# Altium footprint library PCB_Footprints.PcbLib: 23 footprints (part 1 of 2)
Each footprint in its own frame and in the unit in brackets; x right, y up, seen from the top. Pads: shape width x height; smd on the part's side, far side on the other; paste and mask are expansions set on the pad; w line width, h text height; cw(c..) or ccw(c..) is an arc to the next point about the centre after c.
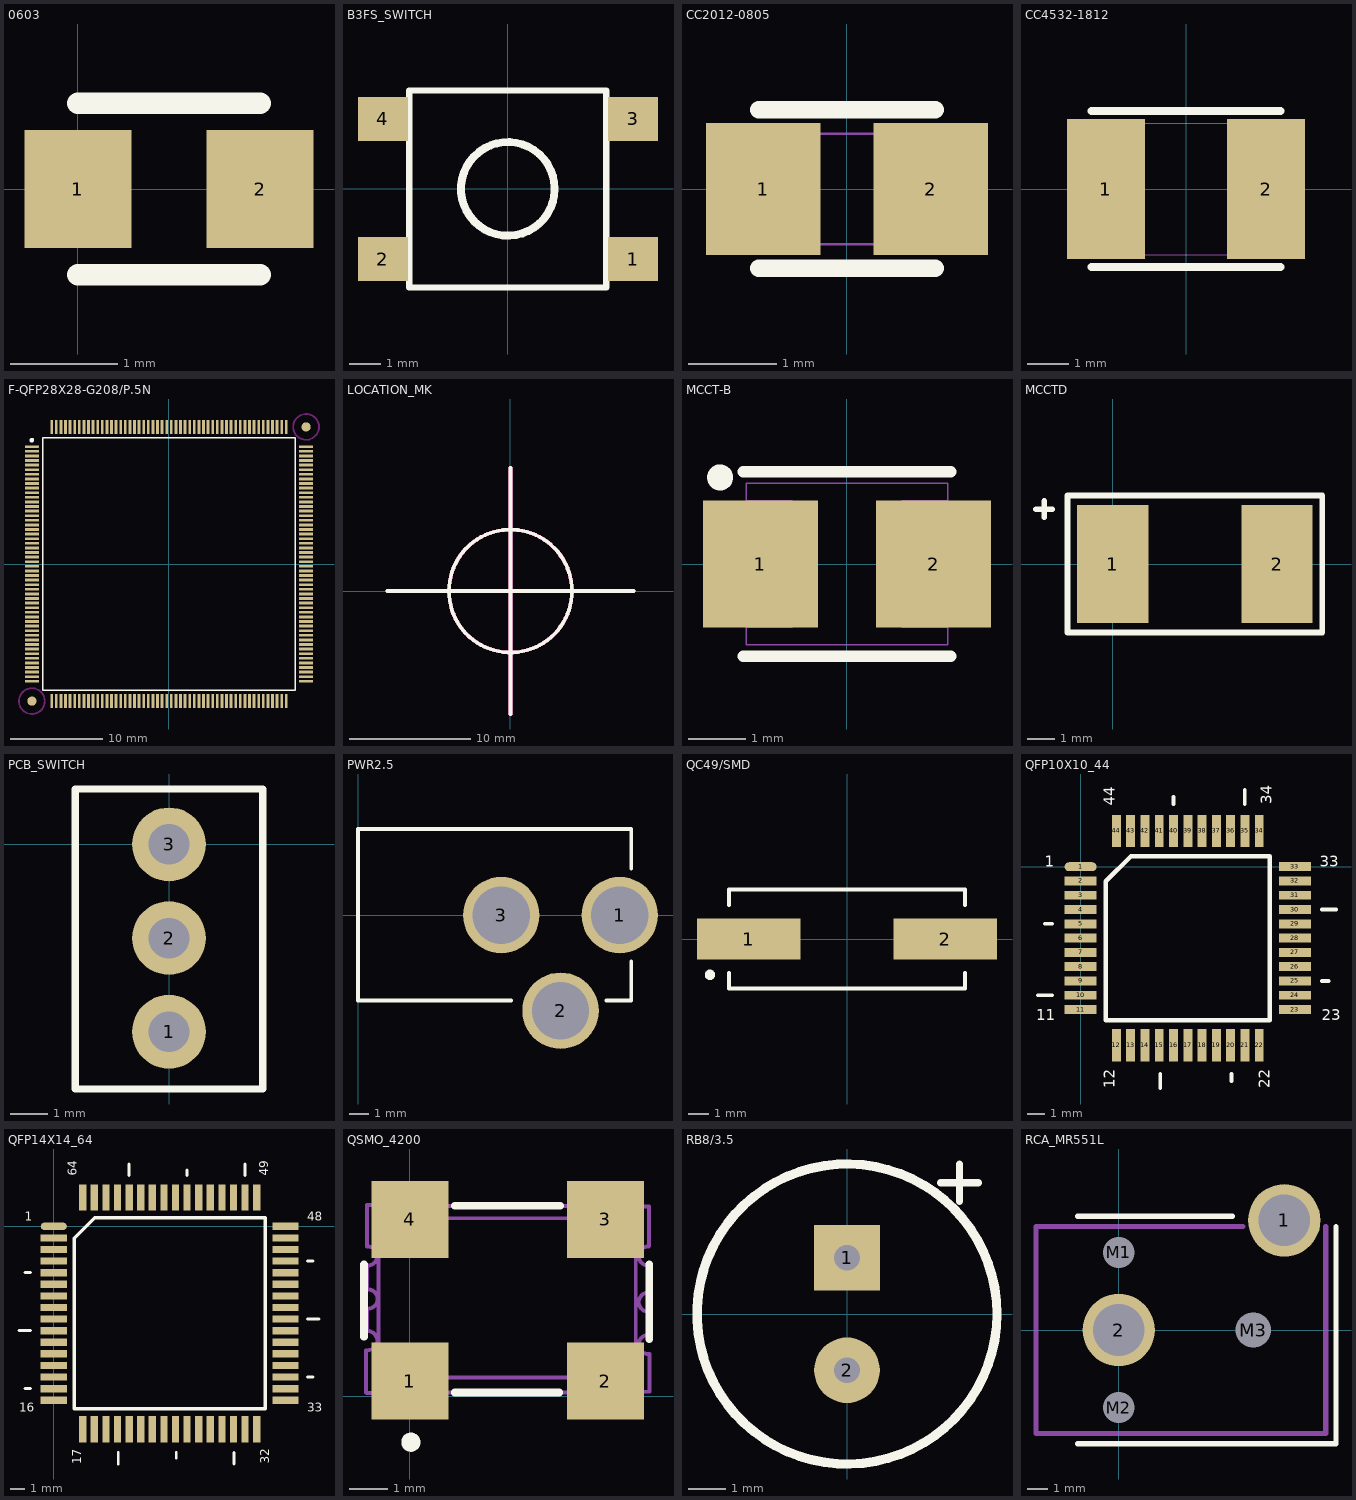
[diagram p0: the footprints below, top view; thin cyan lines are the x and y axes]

## 0603 [mm]
pads (2):
  rect 1x1.1 smd: 1(0,0) 2(1.7,0)
Top Overlay:
  lines w0.203: 0,-0.8 1.7,-0.8 ; 0,0.8 1.7,0.8

## B3FS_SWITCH [mm]
pads (4):
  rect 1.6x1.4 smd: 1(4.01,-2.25) 2(-4,-2.25) 3(4.01,2.24) 4(-4,2.24)
Top Overlay:
  circle w0.254: c0,0 r1.5
  lines w0.2: -3.16,-3.16 -3.16,3.15 3.15,3.15 3.15,-3.16 -3.16,-3.16

## CC2012-0805 [mm]
pads (2):
  rect 1.3x1.5 smd: 1(-0.95,0) 2(0.95,0)
Top Overlay:
  lines w0.2: -1,-0.9 1,-0.9 ; -1,0.9 1,0.9
Mechanical 15:
  lines w0.025: -0.975,-0.625 -0.975,0.625 0.975,0.625 0.975,-0.625 -0.975,-0.625

## CC4532-1812 [mm]
pads (2):
  rect 1.9x3.4 smd: 1(-1.95,0) 2(1.95,0)
Top Overlay:
  lines w0.2: -2.3,-1.9 2.3,-1.9 ; -2.3,1.9 2.3,1.9
Mechanical 15:
  lines w0.025: -2.25,-1.6 -2.25,1.6 2.25,1.6 2.25,-1.6 -2.25,-1.6

## F-QFP28X28-G208/P.5N [mm]
pads (210):
  oval 1.55x0.3 smd: 1(-14.899,12.751)
  rect 1.55x0.3 smd: 2(-14.899,12.251) 3(-14.899,11.751) 4(-14.899,11.251) 5(-14.899,10.751) 6(-14.899,10.251) 7(-14.899,9.751) 8(-14.899,9.251) 9(-14.899,8.751) 10(-14.899,8.251) 11(-14.899,7.751) 12(-14.899,7.251) 13(-14.899,6.751) 14(-14.899,6.251) 15(-14.899,5.751) 16(-14.899,5.251) 17(-14.899,4.751) 18(-14.899,4.251) 19(-14.899,3.751) 20(-14.899,3.251) 21(-14.899,2.751) 22(-14.899,2.251) 23(-14.899,1.751) 24(-14.899,1.251) 25(-14.899,0.751) 26(-14.899,0.251) 27(-14.899,-0.249) 28(-14.899,-0.749) 29(-14.899,-1.249) 30(-14.899,-1.749) 31(-14.899,-2.249) 32(-14.899,-2.749) 33(-14.899,-3.249) 34(-14.899,-3.749) 35(-14.899,-4.249) 36(-14.899,-4.749) 37(-14.899,-5.249) 38(-14.899,-5.749) 39(-14.899,-6.249) 40(-14.899,-6.749) 41(-14.899,-7.249) 42(-14.899,-7.749) 43(-14.899,-8.249) 44(-14.899,-8.749) 45(-14.899,-9.249) 46(-14.899,-9.749) 47(-14.899,-10.249) 48(-14.899,-10.749) 49(-14.899,-11.249) 50(-14.899,-11.749) 51(-14.899,-12.249) 52(-14.899,-12.749) 105(14.901,-12.749) 106(14.901,-12.249) 107(14.901,-11.749) 108(14.901,-11.249) 109(14.901,-10.749) 110(14.901,-10.249) 111(14.901,-9.749) 112(14.901,-9.249) 113(14.901,-8.749) 114(14.901,-8.249) 115(14.901,-7.749) 116(14.901,-7.249) 117(14.901,-6.749) 118(14.901,-6.249) 119(14.901,-5.749) 120(14.901,-5.249) 121(14.901,-4.749) 122(14.901,-4.249) 123(14.901,-3.749) 124(14.901,-3.249) 125(14.901,-2.749) 126(14.901,-2.249) 127(14.901,-1.749) 128(14.901,-1.249) 129(14.901,-0.749) 130(14.901,-0.249) 131(14.901,0.251) 132(14.901,0.751) 133(14.901,1.251) 134(14.901,1.751) 135(14.901,2.251) 136(14.901,2.751) 137(14.901,3.251) 138(14.901,3.751) 139(14.901,4.251) 140(14.901,4.751) 141(14.901,5.251) 142(14.901,5.751) 143(14.901,6.251) 144(14.901,6.751) 145(14.901,7.251) 146(14.901,7.751) 147(14.901,8.251) 148(14.901,8.751) 149(14.901,9.251) 150(14.901,9.751) 151(14.901,10.251) 152(14.901,10.751) 153(14.901,11.251) 154(14.901,11.751) 155(14.901,12.251) 156(14.901,12.751)
  rect 0.3x1.55 smd: 53(-12.749,-14.899) 54(-12.249,-14.899) 55(-11.749,-14.899) 56(-11.249,-14.899) 57(-10.749,-14.899) 58(-10.249,-14.899) 59(-9.749,-14.899) 60(-9.249,-14.899) 61(-8.749,-14.899) 62(-8.249,-14.899) 63(-7.749,-14.899) 64(-7.249,-14.899) 65(-6.749,-14.899) 66(-6.249,-14.899) 67(-5.749,-14.899) 68(-5.249,-14.899) 69(-4.749,-14.899) 70(-4.249,-14.899) 71(-3.749,-14.899) 72(-3.249,-14.899) 73(-2.749,-14.899) 74(-2.249,-14.899) 75(-1.749,-14.899) 76(-1.249,-14.899) 77(-0.749,-14.899) 78(-0.249,-14.899) 79(0.251,-14.899) 80(0.751,-14.899) 81(1.251,-14.899) 82(1.751,-14.899) 83(2.251,-14.899) 84(2.751,-14.899) 85(3.251,-14.899) 86(3.751,-14.899) 87(4.251,-14.899) 88(4.751,-14.899) 89(5.251,-14.899) 90(5.751,-14.899) 91(6.251,-14.899) 92(6.751,-14.899) 93(7.251,-14.899) 94(7.751,-14.899) 95(8.251,-14.899) 96(8.751,-14.899) 97(9.251,-14.899) 98(9.751,-14.899) 99(10.251,-14.899) 100(10.751,-14.899) 101(11.251,-14.899) 102(11.751,-14.899) 103(12.251,-14.899) 104(12.751,-14.899) 157(12.751,14.901) 158(12.251,14.901) 159(11.751,14.901) 160(11.251,14.901) 161(10.751,14.901) 162(10.251,14.901) 163(9.751,14.901) 164(9.251,14.901) 165(8.751,14.901) 166(8.251,14.901) 167(7.751,14.901) 168(7.251,14.901) 169(6.751,14.901) 170(6.251,14.901) 171(5.751,14.901) 172(5.251,14.901) 173(4.751,14.901) 174(4.251,14.901) 175(3.751,14.901) 176(3.251,14.901) 177(2.751,14.901) 178(2.251,14.901) 179(1.751,14.901) 180(1.251,14.901) 181(0.751,14.901) 182(0.251,14.901) 183(-0.249,14.901) 184(-0.749,14.901) 185(-1.249,14.901) 186(-1.749,14.901) 187(-2.249,14.901) 188(-2.749,14.901) 189(-3.249,14.901) 190(-3.749,14.901) 191(-4.249,14.901) 192(-4.749,14.901) 193(-5.249,14.901) 194(-5.749,14.901) 195(-6.249,14.901) 196(-6.749,14.901) 197(-7.249,14.901) 198(-7.749,14.901) 199(-8.249,14.901) 200(-8.749,14.901) 201(-9.249,14.901) 202(-9.749,14.901) 203(-10.249,14.901) 204(-10.749,14.901) 205(-11.249,14.901) 206(-11.749,14.901) 207(-12.249,14.901) 208(-12.749,14.901)
  round 1 smd: FID1(-14.899,-14.899) FID2(14.901,14.901)
Top Layer keep-out:
  circle w0.2: c-14.899,-14.899 r1.4
  circle w0.2: c14.901,14.901 r1.4
Top Overlay:
  circle w0.25: c-14.899,13.451 r0.125
  lines w0.2: -13.724,-13.724 -13.724,13.726 13.726,13.726 13.726,-13.724 -13.724,-13.724

## LOCATION_MK [mm]
Top Layer:
  circle w0.305: c0,0 r5.08
  circle w0.305: c0,0 r5.08
  lines w0.305: -10.16,0 10.16,0 -10.16,0 ; 0,-10.16 0,10.16 0,-10.16
Mid-Layer 1:
  circle w0.305: c0,0 r5.08
  lines w0.305: -10.16,0 10.16,0 ; 0,-10.16 0,10.16
Mid-Layer 14:
  circle w0.305: c0,0 r5.08
  lines w0.305: -10.16,0 10.16,0 ; 0,-10.16 0,10.16
Bottom Layer:
  circle w0.305: c0,0 r5.08
  circle w0.305: c0,0 r5.08
  lines w0.305: -10.16,0 10.16,0 -10.16,0 ; 0,-10.16 0,10.16 0,-10.16
Top Overlay:
  circle w0.305: c0,0 r5.08
  circle w0.305: c0,0 r5.08
  lines w0.305: -10.16,0 10.16,0 -10.16,0 ; 0,-10.16 0,10.16 0,-10.16
Bottom Overlay:
  circle w0.305: c0,0 r5.08
  circle w0.305: c0,0 r5.08
  lines w0.305: -10.16,0 10.16,0 -10.16,0 ; 0,-10.16 0,10.16 0,-10.16
Top Paste:
  circle w0.305: c0,0 r5.08
  circle w0.305: c0,0 r5.08
  lines w0.305: -10.16,0 10.16,0 -10.16,0 ; 0,-10.16 0,10.16 0,-10.16
Bottom Paste:
  circle w0.305: c0,0 r5.08
  circle w0.305: c0,0 r5.08
  lines w0.305: -10.16,0 10.16,0 -10.16,0 ; 0,-10.16 0,10.16 0,-10.16
Top Solder:
  circle w0.305: c0,0 r5.08
  circle w0.305: c0,0 r5.08
  lines w0.305: -10.16,0 10.16,0 -10.16,0 ; 0,-10.16 0,10.16 0,-10.16
Bottom Solder:
  circle w0.305: c0,0 r5.08
  circle w0.305: c0,0 r5.08
  lines w0.305: -10.16,0 10.16,0 -10.16,0 ; 0,-10.16 0,10.16 0,-10.16
Internal Plane 1:
  circle w0.305: c0,0 r5.08
  circle w0.305: c0,0 r5.08
  lines w0.305: -10.16,0 10.16,0 -10.16,0 ; 0,-10.16 0,10.16 0,-10.16
Internal Plane 2:
  circle w0.305: c0,0 r5.08
  circle w0.305: c0,0 r5.08
  lines w0.305: -10.16,0 10.16,0 -10.16,0 ; 0,-10.16 0,10.16 0,-10.16
Drill Guide:
  circle w0.305: c0,0 r5.08
  circle w0.305: c0,0 r5.08
  lines w0.305: -10.16,0 10.16,0 -10.16,0 ; 0,-10.16 0,10.16 0,-10.16
Keep-Out Layer:
  circle w0.305: c0,0 r5.08
  circle w0.305: c0,0 r5.08
  lines w0.305: -10.16,0 10.16,0 -10.16,0 ; 0,-10.16 0,10.16 0,-10.16
Mechanical 1:
  circle w0.305: c0,0 r5.08
  circle w0.305: c0,0 r5.08
  lines w0.305: -10.16,0 10.16,0 -10.16,0 ; 0,-10.16 0,10.16 0,-10.16
Mechanical 4:
  circle w0.305: c0,0 r5.08
  circle w0.305: c0,0 r5.08
  lines w0.305: -10.16,0 10.16,0 -10.16,0 ; 0,-10.16 0,10.16 0,-10.16
Drill Drawing:
  circle w0.305: c0,0 r5.08
  circle w0.305: c0,0 r5.08
  lines w0.305: -10.16,0 10.16,0 -10.16,0 ; 0,-10.16 0,10.16 0,-10.16

## MCCT-B [mm]
pads (2):
  rect 2x2.2 smd: 1(-1.5,0) 2(1.5,0)
Top Overlay:
  circle w0.25: c-2.2,1.5 r0.1
  lines w0.2: -1.8,-1.6 1.8,-1.6 ; -1.8,1.6 1.8,1.6
Mechanical 15:
  lines w0.025: -1.75,-1.1 -0.95,-1.1 -0.95,1.1 -1.75,1.1 ; 1.75,-1.1 0.95,-1.1 0.95,1.1 1.75,1.1 ; -1.75,-1.4 1.75,-1.4 1.75,1.4 -1.75,1.4 -1.75,-1.4

## MCCTD [mm]
pads (2):
  rect 2.6x4.3 smd: 1(0,0) 2(6,0)
Top Overlay:
  lines w0.203: -2.8,2 -2.2,2 ; -2.5,1.7 -2.5,2.3 ; -1.65,-2.5 -1.65,0 -1.65,2.5 7.65,2.5 7.65,-2.5 -1.65,-2.5

## PCB_SWITCH [mm]
pads (3):
  round 2 hole 1.1: 1(0,-5.08) 2(0,-2.54) 3(0,0)
Top Overlay:
  lines w0.2: -2.54,-6.63 2.54,-6.63 2.54,1.5 -2.54,1.5 -2.54,-6.63

## PWR2.5 [mm]
pads (3):
  round 4 hole 3: 1(13.7,0) 2(10.6,-5) 3(7.5,0)
Top Overlay:
  lines w0.2: 8,-4.475 0,-4.475 0,0.025 0,4.5 14.3,4.5 14.3,2.425 ; 13,-4.475 14.3,-4.475 14.3,-2.425

## QC49/SMD [mm]
pads (2):
  rect 5x2 smd: 1(-4.75,0) 2(4.75,0)
Top Overlay:
  circle w0.25: c-6.625,-1.73 r0.125
  lines w0.2: -5.7,-1.65 -5.7,-2.4 5.7,-2.4 5.7,-1.65 ; -5.7,1.65 -5.7,2.4 5.7,2.4 5.7,1.65

## QFP10X10_44 [mm]
pads (44):
  oval 1.8x0.5 smd: 1(0,0)
  rect 1.8x0.5 smd: 2(0,-0.8) 3(0,-1.6) 4(0,-2.4) 5(0,-3.2) 6(0,-4) 7(0,-4.8) 8(0,-5.6) 9(0,-6.4) 10(0,-7.2) 11(0,-8) 23(12,-8) 24(12,-7.2) 25(12,-6.4) 26(12,-5.6) 27(12,-4.8) 28(12,-4) 29(12,-3.2) 30(12,-2.4) 31(12,-1.6) 32(12,-0.8) 33(12,0)
  rect 0.5x1.8 smd: 12(2,-10) 13(2.8,-10) 14(3.6,-10) 15(4.4,-10) 16(5.2,-10) 17(6,-10) 18(6.8,-10) 19(7.6,-10) 20(8.4,-10) 21(9.2,-10) 22(10,-10) 34(10,2) 35(9.2,2) 36(8.4,2) 37(7.6,2) 38(6.8,2) 39(6,2) 40(5.2,2) 41(4.4,2) 42(3.6,2) 43(2.8,2) 44(2,2)
Top Overlay:
  lines w0.203: -2.4,-7.2 -1.6,-7.2 ; -2,-3.2 -1.6,-3.2 ; 4.45,-12.4 4.45,-11.6 ; 5.2,3.5 5.2,3.9 ; 8.45,-12 8.45,-11.6 ; 9.2,3.5 9.2,4.3 ; 13.5,-6.4 13.9,-6.4 ; 13.5,-2.4 14.3,-2.4
  lines w0.25: 1.41,-8.59 10.59,-8.59 10.59,0.59 2.82,0.59 1.41,-0.82 1.41,-8.59
  text "44" at 1.9,3.4 h0.61
  text "34" at 10.7,3.5 h0.61
  text "11" at -2.5,-8.6 h0.61
  text "1" at -2,0 h0.61
  text "22" at 10.6,-12.4 h0.61
  text "12" at 1.9,-12.4 h0.61
  text "33" at 13.4,0 h0.61
  text "23" at 13.5,-8.6 h0.61

## QFP14X14_64 [mm]
pads (64):
  oval 1.8x0.5 smd: 1(0,0)
  rect 1.8x0.5 smd: 2(0,-0.8) 3(0,-1.6) 4(0,-2.4) 5(0,-3.2) 6(0,-4) 7(0,-4.8) 8(0,-5.6) 9(0,-6.4) 10(0,-7.2) 11(0,-8) 12(0,-8.8) 13(0,-9.6) 14(0,-10.4) 15(0,-11.2) 16(0,-12) 33(16,-12) 34(16,-11.2) 35(16,-10.4) 36(16,-9.6) 37(16,-8.8) 38(16,-8) 39(16,-7.2) 40(16,-6.4) 41(16,-5.6) 42(16,-4.8) 43(16,-4) 44(16,-3.2) 45(16,-2.4) 46(16,-1.6) 47(16,-0.8) 48(16,0)
  rect 0.5x1.8 smd: 17(2,-14) 18(2.8,-14) 19(3.6,-14) 20(4.4,-14) 21(5.2,-14) 22(6,-14) 23(6.8,-14) 24(7.6,-14) 25(8.4,-14) 26(9.2,-14) 27(10,-14) 28(10.8,-14) 29(11.6,-14) 30(12.4,-14) 31(13.2,-14) 32(14,-14) 49(14,2) 50(13.2,2) 51(12.4,2) 52(11.6,2) 53(10.8,2) 54(10,2) 55(9.2,2) 56(8.4,2) 57(7.6,2) 58(6.8,2) 59(6,2) 60(5.2,2) 61(4.4,2) 62(3.6,2) 63(2.8,2) 64(2,2)
Top Overlay:
  lines w0.203: -2.4,-7.2 -1.6,-7.2 ; -2,-11.2 -1.6,-11.2 ; -2,-3.2 -1.6,-3.2 ; 4.45,-16.4 4.45,-15.6 ; 5.2,3.5 5.2,4.3 ; 8.45,-16 8.45,-15.6 ; 9.2,3.5 9.2,3.9 ; 12.45,-16.4 12.45,-15.6 ; 13.2,3.5 13.2,4.3 ; 17.5,-10.4 17.9,-10.4 ; 17.5,-6.4 18.3,-6.4 ; 17.5,-2.4 17.9,-2.4
  lines w0.25: 1.41,-12.59 14.59,-12.59 14.59,0.59 2.82,0.59 1.41,-0.82 1.41,-12.59
  text "1" at -2,0.4 h0.61
  text "16" at -2.4,-12.8 h0.61
  text "17" at 1.9,-16.4 h0.61
  text "32" at 14.85,-16.4 h0.61
  text "33" at 17.5,-12.8 h0.61
  text "48" at 17.5,0.4 h0.61
  text "49" at 14.8,3.5 h0.61
  text "64" at 1.6,3.5 h0.61

## QSMO_4200 [mm]
pads (4):
  rect 2x2 smd: 1(0,0.4) 2(5.08,0.4) 3(5.08,4.6) 4(0,4.6)
Top Overlay:
  circle w0.25: c0.025,-1.19 r0.125
  lines w0.2: -1.194,1.549 -1.194,3.429 ; 1.162,4.953 3.912,4.953 ; 1.168,0.102 3.886,0.102 ; 6.223,1.489 6.223,3.429
Mechanical 15:
  lines w0.1: -1.143,0.102 -1.143,1.194 ; -1.12,0.09 -0.27,0.09 -0.29,0.11 ; -1.12,3.9 -1.12,4.98 -0.26,4.98 ; -1.118,1.702 -1.118,2.286 ; -1.118,2.794 -1.118,3.378 ; -1.1,1.2 ccw(c-1.1,1.45) -1.1,1.7 ; -1.1,3.4 ccw(c-1.1,3.65) -1.1,3.9 ; -1.09,2.28 ccw(c-1.09,2.53) -1.09,2.78 ; -0.83,0.49 5.87,0.49 5.87,4.63 -0.82,4.63 -0.82,3.91 -0.82,0.51 ; -0.3,0.15 cw(c-0.05,0.15) 0.2,0.15 ; -0.23,4.91 ccw(c0.02,4.91) 0.27,4.91 ; 0.19,0.1 4.78,0.1 ; 0.25,4.95 4.87,4.95 ; 4.8,0.16 cw(c5.05,0.16) 5.3,0.16 ; 4.88,4.91 ccw(c5.13,4.91) 5.38,4.91 ; 5.29,0.12 6.23,0.12 6.23,1.1 ; 5.35,4.94 6.22,4.94 6.22,3.91 ; 6.198,1.62 6.198,2.184 ; 6.2,1.1 cw(c6.2,1.35) 6.2,1.6 ; 6.2,2.2 cw(c6.2,2.45) 6.2,2.7 ; 6.2,3.4 cw(c6.2,3.65) 6.2,3.9 ; 6.223,2.704 6.223,3.378

## RB8/3.5 [mil]
pads (2):
  rect 70x70 hole 27.56: 1(0,60)
  round 70 hole 27.56: 2(0,-60)
Top Overlay:
  circle w10: c0,0 r160
  lines w7.87: 100,140 140,140 ; 120,120 120,160

## RCA_MR551L [mm] "Schurter RCA PCB Socket (Farnell 152-396)"
pads (5):
  round 3.5 hole 2.5: 1(8,5.3) 2(0,0)
  round 1.3 hole 1.5 unplated: M1(0,3.75) M2(0,-3.75)
  round 1.5 hole 1.7 unplated: M3(6.5,0)
Top Overlay:
  lines w0.254: -2,-5.5 10.5,-5.5 10.5,5 ; -2,5.5 5.5,5.5
Mechanical 1:
  lines w0.254: 6,5 -4,5 -4,-5 10,-5 10,5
